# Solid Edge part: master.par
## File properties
Author: Vicky Raina
Template: Normal.par
Last saved by: CADCIM
Revision: 2
Application: Solid Edge
Accuracy: 0.99
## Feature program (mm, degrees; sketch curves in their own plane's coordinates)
body "unnamed Body 1"
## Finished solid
Body 1: solid body, 75 faces, 214 edges, 140 vertices.
  Faces by surface: cylinder 56, plane 19
  Edges by curve: circle 102, line 100, spline 12
Bounding box of the edges (mm): 7327.900 x 1778.000 x 2844.800, from (-1244.6, -355.6, -1422.4) to (6083.3, 1422.4, 1422.4).
Cylindrical faces by radius (mm): R152.4 x20, R304.8 x2, R330.2 x8, R444.5 x2, R635 x2, R660.4 x2, R800.1 x6, R1473.2 x4, R1828.8 x6, R1981.2 x4
Planar faces by outward normal: +y 5, +z 2, -x 1, -y 5, -z 2, oblique 4
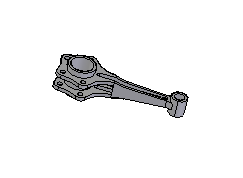
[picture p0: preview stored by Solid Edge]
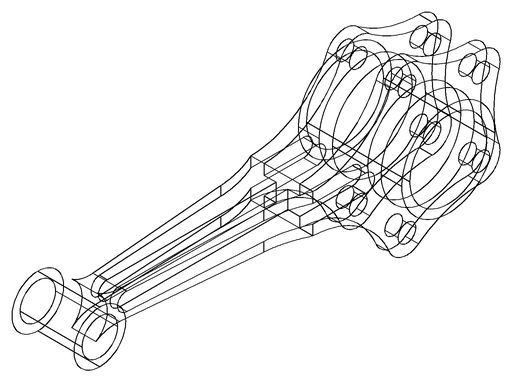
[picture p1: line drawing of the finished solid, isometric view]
